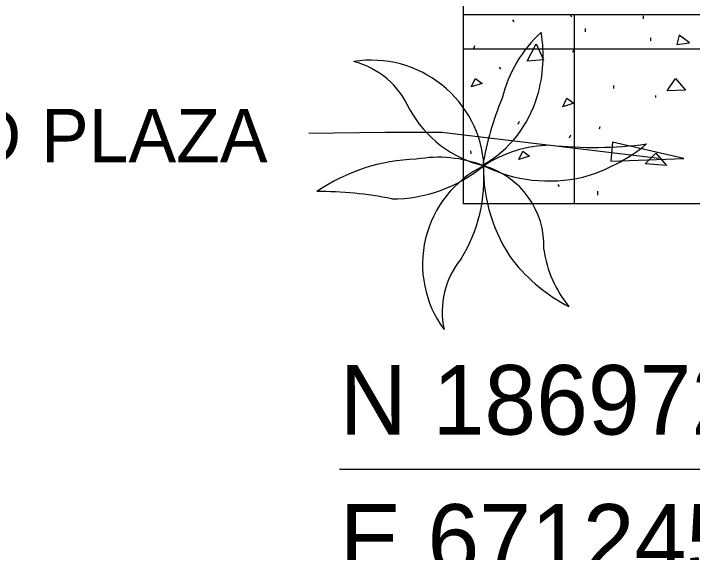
# Model space of a CAD drawing. Extents: x 6712138 to 6712574, y 1869536 to 1870160.
# Drawn here: x 6712395.89 to 6712431.01, y 1869691.03 to 1869718.92 of the extents above; entities that cross this region are included whole.
import ezdxf

# ---------------------------------------------------------------- set-up
doc = ezdxf.new("R2010")
doc.units = 0
for name, color, linetype in [('A-ANNO-TEXT', 7, 'Continuous'), ('A-FLOR-OTLN', 7, 'Continuous'), ('A-FLOR-PATT', 7, 'Continuous'), ('I-WALL', 7, 'Continuous'), ('L-Palm', 7, 'Continuous'), ('L-PLNT-PALM', 7, 'Continuous'), ('L-SITE-PAVE', 7, 'Continuous')]:
    doc.layers.add(name, color=color, linetype=linetype)

# ---------------------------------------------------------------- blocks, each defined once
blk = doc.blocks.new('PALM_1')
at = {"layer": 'L-Palm'}
for centre, radius, start, end in [((0.3859, 0.0987), 0.3422, 132.6801, 166.8111), ((-0.2114, 0.2856), 0.371, 343.7522, 10.043), ((-0.29, -0.0226), 0.2968, 4.0873, 99.2555), ((-0.393, 0.0561), 0.2213, 24.2552, 75.5182), ((-0.1527, 0.2677), 0.3096, 300.1113, 343.9042), ((0.8252, -0.1374), 0.834, 157.8667, 170.5307), ((0.0708, 0.2901), 0.2986, 208.6354, 257.4748), ((0.1868, -0.2705), 0.3242, 91.3382, 124.0385), ((0.2849, 1.1558), 1.1072, 264.5234, 277.6792), ((0.1358, 0.4172), 0.4657, 286.1702, 309.6262), ((-0.1117, -0.3019), 0.3219, 68.8397, 100.8216), ((-0.1563, -0.4706), 0.4851, 91.8686, 124.7845), ((-0.2364, 0.2825), 0.3726, 270.0402, 310.2895), ((0.1346, -0.2597), 0.2886, 116.7925, 216.8342), ((-0.3946, -0.0377), 0.4007, 328.6183, 5.0923), ((0.4257, -0.0051), 0.4212, 179.4834, 215.787), ((-0.0535, -0.2115), 0.2181, 357.6134, 74.5522), ((0.1756, 0.3541), 0.3946, 244.4343, 283.1777), ((-0.4218, -1.0386), 0.9665, 78.9259, 90.6662), ((0.4639, -0.1765), 0.3027, 188.3856, 219.8245), ((0.1198, -0.3852), 0.2213, 141.1268, 192.3899), ((0.4441, 0.0439), 0.4657, 219.354, 242.8101)]:
    blk.add_arc(centre, radius, start, end, dxfattribs=at)

msp = doc.modelspace()

# ---------------------------------------------------------------- linework, layer by layer
at = {"layer": 'A-ANNO-TEXT'}
for p, q in [((6712415.1, 1869712.756), (6712411.164, 1869712.72)), ((6712415.1, 1869712.756), (6712411.164, 1869712.72)), ((6712418.042, 1869712.756), (6712415.1, 1869712.756)), ((6712418.042, 1869712.756), (6712415.1, 1869712.756)), ((6712429.264, 1869711.413), (6712418.042, 1869712.756)), ((6712429.264, 1869711.413), (6712418.042, 1869712.756)), ((6712426.879, 1869712.268), (6712426.784, 1869711.285)), ((6712426.879, 1869712.268), (6712426.784, 1869711.285)), ((6712430.564, 1869711.413), (6712426.879, 1869712.268)), ((6712430.564, 1869711.413), (6712426.879, 1869712.268)), ((6712426.784, 1869711.285), (6712430.564, 1869711.413)), ((6712426.784, 1869711.285), (6712430.564, 1869711.413))]:
    msp.add_line(p, q, dxfattribs=at)
at = {"layer": 'A-FLOR-OTLN'}
msp.add_lwpolyline([(6712251.183, 1869839.781), (6712251.183, 1869722.323), (6712419.14, 1869722.323), (6712419.14, 1869718.864), (6712468.641, 1869718.864), (6712468.641, 1869839.781)], close=True, dxfattribs=at)
at = {"layer": 'A-FLOR-PATT'}
for p, q in [((6712424.678, 1869718.864), (6712424.751, 1869718.751)), ((6712428.469, 1869718.651), (6712428.469, 1869718.811)), ((6712421.691, 1869718.591), (6712421.765, 1869718.484)), ((6712425.468, 1869717.98), (6712425.468, 1869718.14)), ((6712428.852, 1869717.501), (6712428.852, 1869717.661)), ((6712419.691, 1869717.104), (6712419.758, 1869717.264)), ((6712424.825, 1869716.924), (6712424.891, 1869717.084)), ((6712421.005, 1869716.138), (6712421.078, 1869716.038)), ((6712426.946, 1869715.043), (6712426.946, 1869715.203)), ((6712429.116, 1869714.573), (6712429.116, 1869714.683)), ((6712421.991, 1869713.198), (6712422.058, 1869713.358)), ((6712426.196, 1869712.953), (6712426.236, 1869713.073)), ((6712424.651, 1869712.484), (6712424.718, 1869712.638)), ((6712419.525, 1869711.818), (6712419.545, 1869711.658)), ((6712424.045, 1869710.078), (6712424.118, 1869709.971)), ((6712426.116, 1869709.523), (6712426.116, 1869709.723))]:
    msp.add_line(p, q, dxfattribs=at)
for points in [[(6712430.191, 1869717.316), (6712430.861, 1869717.406), (6712430.311, 1869717.796)], [(6712429.706, 1869714.923), (6712430.136, 1869715.553), (6712430.646, 1869714.963)], [(6712428.556, 1869711.143), (6712429.116, 1869711.693), (6712429.656, 1869711.063)]]:
    msp.add_lwpolyline(points, close=True, dxfattribs=at)
for points in [[(6712422.458, 1869716.458), (6712422.931, 1869717.351), (6712423.305, 1869716.524), (6712422.478, 1869716.458)], [(6712419.565, 1869715.131), (6712419.778, 1869715.564), (6712420.125, 1869715.304), (6712419.565, 1869715.131)], [(6712424.305, 1869714.098), (6712424.511, 1869714.538), (6712424.865, 1869714.278), (6712424.305, 1869714.098)], [(6712422.025, 1869711.358), (6712422.231, 1869711.798), (6712422.578, 1869711.538), (6712422.025, 1869711.358)]]:
    msp.add_lwpolyline(points, dxfattribs=at)
at = {"layer": 'I-WALL'}
msp.add_lwpolyline([(6712454.068, 1869695.328), (6712412.753, 1869695.328)], dxfattribs=at)
at = {"layer": 'L-SITE-PAVE'}
for p, q in [((6712419.14, 1869718.864), (6712419.14, 1869709.073)), ((6712424.891, 1869718.864), (6712424.891, 1869709.073)), ((6712424.891, 1869718.864), (6712424.891, 1869709.073)), ((6712479.055, 1869717.073), (6712419.14, 1869717.073)), ((6712479.055, 1869717.073), (6712424.891, 1869717.073)), ((6712479.056, 1869709.073), (6712419.14, 1869709.073)), ((6712479.056, 1869709.073), (6712424.891, 1869709.073))]:
    msp.add_line(p, q, dxfattribs=at)

# ---------------------------------------------------------------- block references
at = {"layer": 'L-PLNT-PALM', "xscale": 19.685039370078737, "yscale": 19.68503937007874, "rotation": -0.36974722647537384}
msp.add_blockref('PALM_1', (6712420.108, 1869711.073), dxfattribs=at)

# ---------------------------------------------------------------- texts
at = {"layer": 'A-ANNO-TEXT'}
msp.add_text('EXTENDED PLAZA ', height=2.76619, dxfattribs=at).set_placement((6712376.141, 1869711.22))
msp.add_text('EXTENDED PLAZA ', height=2.76619, dxfattribs=at).set_placement((6712376.141, 1869711.22))
at = {"layer": 'I-WALL'}
for s, p in [('N 1869723.07', (6712412.753, 1869697.128)), ('E 6712459.89', (6712412.753, 1869689.928))]:
    msp.add_text(s, height=3.6, dxfattribs=at).set_placement(p)

doc.saveas('drawing.dxf')
